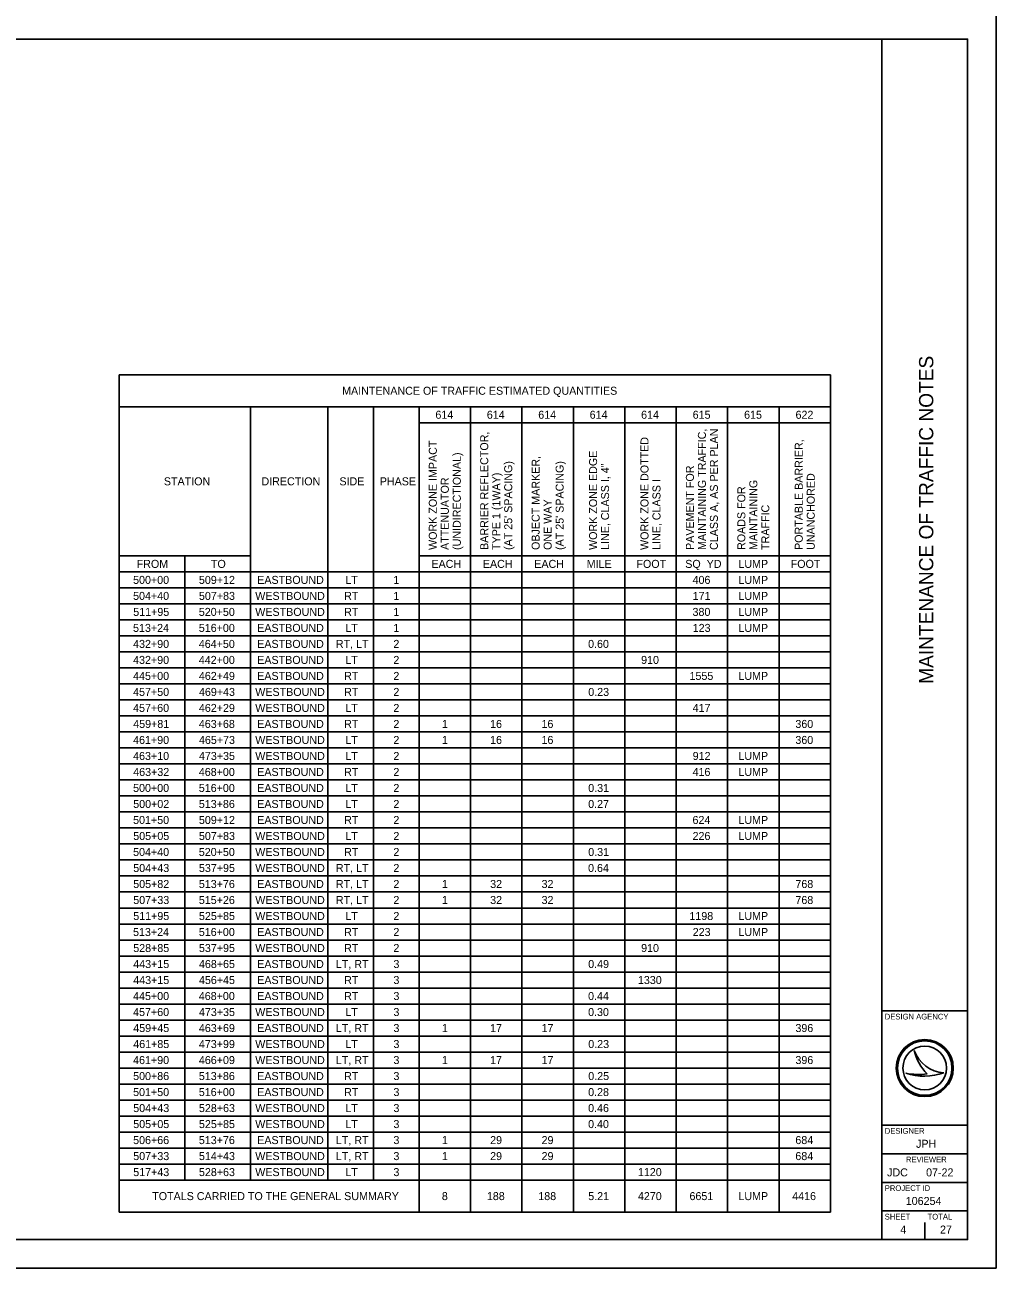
# Model space of a CAD drawing. Extents: x 0 to 5770, y -1320 to 440.
# Drawn here: x 4696.9 to 5036.9, y -914.5 to -479.5 of the extents above; entities that cross this region are included whole.
import ezdxf

# ---------------------------------------------------------------- set-up
doc = ezdxf.new("R2010")
doc.units = 0
for name, color, linetype in [('_CIVIL_CONSTRUCTION', 7, 'Continuous'), ('GE_P_Alignment', 7, 'Continuous'), ('GE_P_Alignment_100_Bearings', 7, 'Continuous'), ('GE_P_Alignment_100_Curve_Data', 7, 'Continuous')]:
    doc.layers.add(name, color=color, linetype=linetype)

msp = doc.modelspace()

# ---------------------------------------------------------------- linework, layer by layer
at = {"layer": '_CIVIL_CONSTRUCTION'}
msp.add_lwpolyline([(4356.9, -914.45), (5036.9, -914.45), (5036.9, -474.45), (4356.9, -474.45)], close=True, dxfattribs=at)
at = {"layer": 'GE_P_Alignment'}
for p, q in [((4996.9, -904.45), (4996.9, -484.45)), ((4996.9, -824.45), (5026.9, -824.45)), ((4996.9, -864.45), (5026.9, -864.45)), ((4996.9, -874.45), (5026.9, -874.45)), ((4996.9, -884.45), (5026.9, -884.45)), ((4996.9, -894.45), (5026.9, -894.45))]:
    msp.add_line(p, q, dxfattribs=at)
msp.add_lwpolyline([(4386.9, -484.45), (5026.9, -484.45), (5026.9, -904.45), (4386.9, -904.45)], close=True, dxfattribs=at)
at = {"layer": 'GE_P_Alignment_100_Bearings'}
for p, q in [((5008.24, -838.26), (5008.25, -838.26)), ((5005.24, -846.26), (5005.24, -846.26)), ((5011.9, -844.45), (5011.9, -844.45)), ((5018.64, -846.08), (5018.64, -846.08)), ((5011.9, -904.45), (5011.9, -898.45)), ((5004.4, -900.95), (5004.4, -900.95))]:
    msp.add_line(p, q, dxfattribs=at)
for radius in [10, 9.54, 9.54, 7.64]:
    msp.add_circle((5011.9, -844.45), radius, dxfattribs=at)
for centre, radius, start, end in [((5019.21, -834.5), 11.6, 198.9257, 198.9319), ((5023.83, -835.05), 15.91, 191.6379, 191.6421), ((5019.21, -834.5), 11.6, 198.9319, 267.1657), ((5023.83, -835.05), 15.91, 191.6421, 226.0947), ((5011.68, -827.05), 20.26, 251.4576, 290.0832), ((5009.86, -821.37), 25.32, 259.4964, 259.4995), ((5011.68, -827.05), 20.26, 251.4527, 251.4576), ((5009.86, -821.37), 25.32, 259.4995, 276.6672)]:
    msp.add_arc(centre, radius, start, end, dxfattribs=at)
at = {"layer": 'GE_P_Alignment_100_Curve_Data'}
for p, q in [((4729.9, -894.85), (4729.9, -601.87)), ((4978.9, -601.87), (4729.9, -601.87)), ((4978.9, -894.85), (4978.9, -601.87)), ((4978.9, -613.07), (4729.9, -613.07)), ((4775.9, -883.65), (4775.9, -613.07)), ((4802.9, -883.65), (4802.9, -613.07)), ((4818.9, -883.65), (4818.9, -613.07)), ((4834.9, -894.85), (4834.9, -613.07)), ((4852.9, -894.85), (4852.9, -613.07)), ((4870.9, -894.85), (4870.9, -613.07)), ((4888.9, -894.85), (4888.9, -613.07)), ((4906.9, -894.85), (4906.9, -613.07)), ((4924.9, -894.85), (4924.9, -613.07)), ((4942.9, -894.85), (4942.9, -613.07)), ((4960.9, -894.85), (4960.9, -613.07)), ((4978.9, -618.67), (4834.9, -618.67)), ((4775.9, -665.25), (4729.9, -665.25)), ((4752.9, -883.65), (4752.9, -665.25)), ((4834.9, -665.25), (4978.9, -665.25)), ((4729.9, -670.85), (4978.9, -670.85)), ((4729.9, -676.45), (4978.9, -676.45)), ((4729.9, -682.05), (4978.9, -682.05)), ((4729.9, -687.65), (4978.9, -687.65)), ((4729.9, -693.25), (4978.9, -693.25)), ((4729.9, -698.85), (4978.9, -698.85)), ((4729.9, -704.45), (4978.9, -704.45)), ((4729.9, -710.05), (4978.9, -710.05)), ((4729.9, -715.65), (4978.9, -715.65)), ((4729.9, -721.25), (4978.9, -721.25)), ((4729.9, -726.85), (4978.9, -726.85)), ((4729.9, -732.45), (4978.9, -732.45)), ((4729.9, -738.05), (4978.9, -738.05)), ((4729.9, -743.65), (4978.9, -743.65)), ((4729.9, -749.25), (4978.9, -749.25)), ((4729.9, -754.85), (4978.9, -754.85)), ((4729.9, -760.45), (4978.9, -760.45)), ((4729.9, -766.05), (4978.9, -766.05)), ((4729.9, -771.65), (4978.9, -771.65)), ((4729.9, -777.25), (4978.9, -777.25)), ((4729.9, -782.85), (4978.9, -782.85)), ((4729.9, -788.45), (4978.9, -788.45)), ((4729.9, -794.05), (4978.9, -794.05)), ((4729.9, -799.65), (4978.9, -799.65)), ((4729.9, -805.25), (4978.9, -805.25)), ((4729.9, -810.85), (4978.9, -810.85)), ((4729.9, -816.45), (4978.9, -816.45)), ((4729.9, -822.05), (4978.9, -822.05)), ((4729.9, -827.65), (4978.9, -827.65)), ((4729.9, -833.25), (4978.9, -833.25)), ((4729.9, -838.85), (4978.9, -838.85)), ((4729.9, -844.45), (4978.9, -844.45)), ((4729.9, -850.05), (4978.9, -850.05)), ((4729.9, -855.65), (4978.9, -855.65)), ((4729.9, -861.25), (4978.9, -861.25)), ((4729.9, -866.85), (4978.9, -866.85)), ((4729.9, -872.45), (4978.9, -872.45)), ((4729.9, -878.05), (4978.9, -878.05)), ((4729.9, -883.65), (4978.9, -883.65)), ((4729.9, -894.85), (4978.9, -894.85))]:
    msp.add_line(p, q, dxfattribs=at)

# ---------------------------------------------------------------- texts
at = {"layer": 'GE_P_Alignment_100_Bearings'}
msp.add_text('MAINTENANCE OF TRAFFIC NOTES', height=5, rotation=90, dxfattribs=at).set_placement((5014.9, -710.02))
for s, height, p in [('DESIGN AGENCY', 2, (4997.9, -827.45)), ('DESIGNER', 2, (4997.9, -867.45)), ('JPH', 2.8, (5008.86, -872.35)), ('REVIEWER', 2, (5005.33, -877.45)), ('JDC', 2.8, (4998.72, -882.35)), ('07-22', 2.8, (5012.37, -882.35)), ('PROJECT ID', 2, (4997.9, -887.45)), ('106254', 2.8, (5005.25, -892.35)), ('SHEET', 2, (4997.9, -897.45)), ('TOTAL', 2, (5012.9, -897.45)), ('4', 2.8, (5003.34, -902.35)), ('27', 2.8, (5017.26, -902.35))]:
    msp.add_text(s, height=height, dxfattribs=at).set_placement(p)
at = {"layer": 'GE_P_Alignment_100_Curve_Data'}
for s, p in [('MAINTENANCE OF TRAFFIC ESTIMATED QUANTITIES', (4807.96, -608.87)), ('614', (4840.61, -617.27)), ('614', (4858.61, -617.27)), ('614', (4876.61, -617.27)), ('614', (4894.61, -617.27)), ('614', (4912.61, -617.27)), ('615', (4930.67, -617.27)), ('615', (4948.67, -617.27)), ('622', (4966.67, -617.27)), ('STATION', (4745.56, -640.56)), ('DIRECTION', (4779.72, -640.56)), ('SIDE', (4807.01, -640.56)), ('PHASE', (4821.13, -640.56)), ('FROM', (4736.04, -669.45)), ('TO', (4762.03, -669.45)), ('EACH', (4839.22, -669.45)), ('EACH', (4857.22, -669.45)), ('EACH', (4875.22, -669.45)), ('MILE', (4893.57, -669.45)), ('FOOT', (4910.98, -669.45)), ('SQ  YD', (4928.07, -669.45)), ('LUMP', (4946.67, -669.45)), ('FOOT', (4964.98, -669.45)), ('500+00', (4734.79, -675.05)), ('509+12', (4757.83, -675.05)), ('EASTBOUND', (4778.24, -675.05)), ('LT', (4809.07, -675.05)), ('1', (4825.9, -675.05)), ('406', (4930.63, -675.05)), ('LUMP', (4946.67, -675.05)), ('504+40', (4734.79, -680.65)), ('507+83', (4757.84, -680.65)), ('WESTBOUND', (4777.55, -680.65)), ('RT', (4808.66, -680.65)), ('1', (4825.9, -680.65)), ('171', (4930.66, -680.65)), ('LUMP', (4946.67, -680.65)), ('511+95', (4734.84, -686.25)), ('520+50', (4757.79, -686.25)), ('WESTBOUND', (4777.55, -686.25)), ('RT', (4808.66, -686.25)), ('1', (4825.9, -686.25)), ('380', (4930.62, -686.25)), ('LUMP', (4946.67, -686.25)), ('513+24', (4734.77, -691.85)), ('516+00', (4757.79, -691.85)), ('EASTBOUND', (4778.24, -691.85)), ('LT', (4809.07, -691.85)), ('1', (4825.9, -691.85)), ('123', (4930.68, -691.85)), ('LUMP', (4946.67, -691.85)), ('432+90', (4734.79, -697.45)), ('464+50', (4757.79, -697.45)), ('EASTBOUND', (4778.24, -697.45)), ('RT, LT', (4805.77, -697.45)), ('2', (4825.9, -697.45)), ('0.60', (4894.06, -697.45)), ('432+90', (4734.79, -703.05)), ('442+00', (4757.79, -703.05)), ('EASTBOUND', (4778.24, -703.05)), ('LT', (4809.07, -703.05)), ('2', (4825.9, -703.05)), ('910', (4912.62, -703.05)), ('445+00', (4734.79, -708.65)), ('462+49', (4757.82, -708.65)), ('EASTBOUND', (4778.24, -708.65)), ('RT', (4808.66, -708.65)), ('2', (4825.9, -708.65)), ('1555', (4929.56, -708.65)), ('LUMP', (4946.67, -708.65)), ('457+50', (4734.79, -714.25)), ('469+43', (4757.84, -714.25)), ('WESTBOUND', (4777.55, -714.25)), ('RT', (4808.66, -714.25)), ('2', (4825.9, -714.25)), ('0.23', (4894.12, -714.25)), ('457+60', (4734.79, -719.85)), ('462+29', (4757.82, -719.85)), ('WESTBOUND', (4777.55, -719.85)), ('LT', (4809.07, -719.85)), ('2', (4825.9, -719.85)), ('417', (4930.65, -719.85)), ('459+81', (4734.83, -725.45)), ('463+68', (4757.8, -725.45)), ('EASTBOUND', (4778.24, -725.45)), ('RT', (4808.66, -725.45)), ('2', (4825.9, -725.45)), ('1', (4842.9, -725.45)), ('16', (4859.75, -725.45)), ('16', (4877.75, -725.45)), ('360', (4966.62, -725.45)), ('461+90', (4734.79, -731.05)), ('465+73', (4757.84, -731.05)), ('WESTBOUND', (4777.55, -731.05)), ('LT', (4809.07, -731.05)), ('2', (4825.9, -731.05)), ('1', (4842.9, -731.05)), ('16', (4859.75, -731.05)), ('16', (4877.75, -731.05)), ('360', (4966.62, -731.05)), ('463+10', (4734.79, -736.65)), ('473+35', (4757.84, -736.65)), ('WESTBOUND', (4777.55, -736.65)), ('LT', (4809.07, -736.65)), ('2', (4825.9, -736.65)), ('912', (4930.67, -736.65)), ('LUMP', (4946.67, -736.65)), ('463+32', (4734.83, -742.25)), ('468+00', (4757.79, -742.25)), ('EASTBOUND', (4778.24, -742.25)), ('RT', (4808.66, -742.25)), ('2', (4825.9, -742.25)), ('416', (4930.63, -742.25)), ('LUMP', (4946.67, -742.25)), ('500+00', (4734.79, -747.85)), ('516+00', (4757.79, -747.85)), ('EASTBOUND', (4778.24, -747.85)), ('LT', (4809.07, -747.85)), ('2', (4825.9, -747.85)), ('0.31', (4894.11, -747.85)), ('500+02', (4734.83, -753.45)), ('513+86', (4757.8, -753.45)), ('EASTBOUND', (4778.24, -753.45)), ('LT', (4809.07, -753.45)), ('2', (4825.9, -753.45)), ('0.27', (4894.09, -753.45)), ('501+50', (4734.79, -759.05)), ('509+12', (4757.83, -759.05)), ('EASTBOUND', (4778.24, -759.05)), ('RT', (4808.66, -759.05)), ('2', (4825.9, -759.05)), ('624', (4930.61, -759.05)), ('LUMP', (4946.67, -759.05)), ('505+05', (4734.84, -764.65)), ('507+83', (4757.84, -764.65)), ('WESTBOUND', (4777.55, -764.65)), ('LT', (4809.07, -764.65)), ('2', (4825.9, -764.65)), ('226', (4930.63, -764.65)), ('LUMP', (4946.67, -764.65)), ('504+40', (4734.79, -770.25)), ('520+50', (4757.79, -770.25)), ('WESTBOUND', (4777.55, -770.25)), ('RT', (4808.66, -770.25)), ('2', (4825.9, -770.25)), ('0.31', (4894.11, -770.25)), ('504+43', (4734.84, -775.85)), ('537+95', (4757.84, -775.85)), ('WESTBOUND', (4777.55, -775.85)), ('RT, LT', (4805.77, -775.85)), ('2', (4825.9, -775.85)), ('0.64', (4894.05, -775.85)), ('505+82', (4734.83, -781.45)), ('513+76', (4757.8, -781.45)), ('EASTBOUND', (4778.24, -781.45)), ('2', (4825.9, -781.45)), ('32', (4859.78, -781.45)), ('32', (4877.78, -781.45)), ('768', (4966.63, -781.45)), ('RT, LT', (4805.77, -781.45)), ('1', (4842.9, -781.45)), ('507+33', (4734.84, -787.05)), ('515+26', (4757.8, -787.05)), ('WESTBOUND', (4777.55, -787.05)), ('RT, LT', (4805.77, -787.05)), ('2', (4825.9, -787.05)), ('1', (4842.9, -787.05)), ('32', (4859.78, -787.05)), ('32', (4877.78, -787.05)), ('768', (4966.63, -787.05)), ('511+95', (4734.84, -792.65)), ('525+85', (4757.84, -792.65)), ('WESTBOUND', (4777.55, -792.65)), ('LT', (4809.07, -792.65)), ('2', (4825.9, -792.65)), ('1198', (4929.52, -792.65)), ('LUMP', (4946.67, -792.65)), ('513+24', (4734.77, -798.25)), ('516+00', (4757.79, -798.25)), ('EASTBOUND', (4778.24, -798.25)), ('RT', (4808.66, -798.25)), ('2', (4825.9, -798.25)), ('223', (4930.68, -798.25)), ('LUMP', (4946.67, -798.25)), ('528+85', (4734.84, -803.85)), ('537+95', (4757.84, -803.85)), ('WESTBOUND', (4777.55, -803.85)), ('RT', (4808.66, -803.85)), ('2', (4825.9, -803.85)), ('910', (4912.62, -803.85)), ('443+15', (4734.84, -809.45)), ('468+65', (4757.84, -809.45)), ('EASTBOUND', (4778.24, -809.45)), ('LT, RT', (4805.77, -809.45)), ('3', (4825.91, -809.45)), ('0.49', (4894.1, -809.45)), ('443+15', (4734.84, -815.05)), ('456+45', (4757.84, -815.05)), ('EASTBOUND', (4778.24, -815.05)), ('RT', (4808.66, -815.05)), ('3', (4825.91, -815.05)), ('1330', (4911.5, -815.05)), ('445+00', (4734.79, -820.65)), ('468+00', (4757.79, -820.65)), ('EASTBOUND', (4778.24, -820.65)), ('RT', (4808.66, -820.65)), ('3', (4825.91, -820.65)), ('0.44', (4894.05, -820.65)), ('457+60', (4734.79, -826.25)), ('473+35', (4757.84, -826.25)), ('WESTBOUND', (4777.55, -826.25)), ('LT', (4809.07, -826.25)), ('3', (4825.91, -826.25)), ('0.30', (4894.06, -826.25)), ('459+45', (4734.84, -831.85)), ('463+69', (4757.82, -831.85)), ('EASTBOUND', (4778.24, -831.85)), ('LT, RT', (4805.77, -831.85)), ('3', (4825.91, -831.85)), ('1', (4842.9, -831.85)), ('17', (4859.76, -831.85)), ('17', (4877.76, -831.85)), ('396', (4966.63, -831.85)), ('461+85', (4734.84, -837.45)), ('473+99', (4757.82, -837.45)), ('WESTBOUND', (4777.55, -837.45)), ('LT', (4809.07, -837.45)), ('3', (4825.91, -837.45)), ('0.23', (4894.12, -837.45)), ('461+90', (4734.79, -843.05)), ('466+09', (4757.82, -843.05)), ('WESTBOUND', (4777.55, -843.05)), ('LT, RT', (4805.77, -843.05)), ('3', (4825.91, -843.05)), ('1', (4842.9, -843.05)), ('17', (4859.76, -843.05)), ('17', (4877.76, -843.05)), ('396', (4966.63, -843.05)), ('500+86', (4734.8, -848.65)), ('513+86', (4757.8, -848.65)), ('EASTBOUND', (4778.24, -848.65)), ('RT', (4808.66, -848.65)), ('3', (4825.91, -848.65)), ('0.25', (4894.12, -848.65)), ('501+50', (4734.79, -854.25)), ('516+00', (4757.79, -854.25)), ('EASTBOUND', (4778.24, -854.25)), ('RT', (4808.66, -854.25)), ('3', (4825.91, -854.25)), ('0.28', (4894.08, -854.25)), ('504+43', (4734.84, -859.85)), ('528+63', (4757.84, -859.85)), ('WESTBOUND', (4777.55, -859.85)), ('LT', (4809.07, -859.85)), ('3', (4825.91, -859.85)), ('0.46', (4894.07, -859.85)), ('505+05', (4734.84, -865.45)), ('525+85', (4757.84, -865.45)), ('WESTBOUND', (4777.55, -865.45)), ('LT', (4809.07, -865.45)), ('3', (4825.91, -865.45)), ('0.40', (4894.06, -865.45)), ('506+66', (4734.8, -871.05)), ('513+76', (4757.8, -871.05)), ('EASTBOUND', (4778.24, -871.05)), ('LT, RT', (4805.77, -871.05)), ('3', (4825.91, -871.05)), ('1', (4842.9, -871.05)), ('29', (4859.77, -871.05)), ('29', (4877.77, -871.05)), ('684', (4966.61, -871.05)), ('507+33', (4734.84, -876.65)), ('514+43', (4757.84, -876.65)), ('WESTBOUND', (4777.55, -876.65)), ('LT, RT', (4805.77, -876.65)), ('3', (4825.91, -876.65)), ('1', (4842.9, -876.65)), ('29', (4859.77, -876.65)), ('29', (4877.77, -876.65)), ('684', (4966.61, -876.65)), ('517+43', (4734.84, -882.25)), ('528+63', (4757.84, -882.25)), ('WESTBOUND', (4777.55, -882.25)), ('LT', (4809.07, -882.25)), ('3', (4825.91, -882.25)), ('1120', (4911.5, -882.25)), ('TOTALS CARRIED TO THE GENERAL SUMMARY', (4741.48, -890.65)), ('8', (4842.87, -890.65)), ('188', (4858.63, -890.65)), ('188', (4876.63, -890.65)), ('5.21', (4894.11, -890.65)), ('4270', (4911.5, -890.65)), ('6651', (4929.55, -890.65)), ('LUMP', (4946.67, -890.65)), ('4416', (4965.51, -890.65))]:
    msp.add_text(s, height=2.8, dxfattribs=at).set_placement(p)
for s, p in [('MAINTAINING TRAFFIC,', (4935.3, -663.17)), ('CLASS A, AS PER PLAN', (4939.5, -663.17)), ('WORK ZONE IMPACT', (4841.1, -663.17)), ('BARRIER REFLECTOR,', (4859.1, -663.17)), ('WORK ZONE DOTTED', (4915.2, -663.17)), ('PORTABLE BARRIER,', (4969.2, -663.17)), ('(UNIDIRECTIONAL)', (4849.5, -663.17)), ('OBJECT MARKER,', (4877.1, -663.17)), ('WORK ZONE EDGE', (4897.2, -663.17)), ("(AT 25' SPACING)", (4867.5, -663.17)), ("(AT 25' SPACING)", (4885.5, -663.17)), ('LINE, CLASS I, 4"', (4901.4, -663.17)), ('PAVEMENT FOR', (4931.1, -663.17)), ('ATTENUATOR', (4845.3, -663.17)), ('TYPE 1 (1WAY)', (4863.3, -663.17)), ('LINE, CLASS I', (4919.4, -663.17)), ('MAINTAINING', (4953.3, -663.17)), ('UNANCHORED', (4973.4, -663.17)), ('ROADS FOR', (4949.1, -663.17)), ('ONE WAY', (4881.3, -663.17)), ('TRAFFIC', (4957.5, -663.17))]:
    msp.add_text(s, height=2.8, rotation=90, dxfattribs=at).set_placement(p)

doc.saveas('drawing.dxf')
